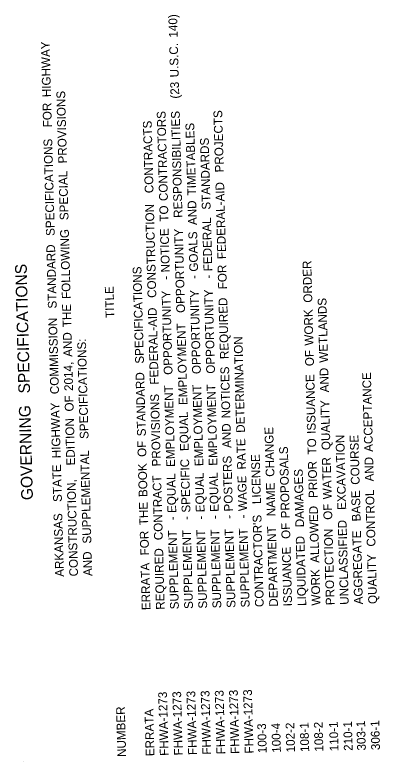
# Model space of a CAD drawing. Extents: x 1930579 to 1931706, y 595585 to 597808.
# Drawn here: x 1930907.1 to 1931148.4, y 595584.7 to 596077.6 of the extents above; entities that cross this region are included whole.
import ezdxf

# ---------------------------------------------------------------- set-up
doc = ezdxf.new("R2010")
doc.units = 0
doc.layers.add('Default', color=7, linetype='Continuous')
doc.layers.add('R_Annotation', color=7, linetype='Continuous')

msp = doc.modelspace()

# ---------------------------------------------------------------- linework, layer by layer
at = {"layer": 'R_Annotation'}
msp.add_line((1930912.52, 595584.68), (1930912.52, 595584.68), dxfattribs=at)

# ---------------------------------------------------------------- texts
at = {"layer": 'Default'}
for s, height, p in [(' 140)', 5.76, (1931014.7, 596060.51)), (' HIGHWAY', 5.76, (1930931.01, 596021.17)), (' U.S.C.', 5.76, (1931015.4, 596034.24)), (' (23', 5.76, (1931015.78, 596020.19)), (' PROVISIONS', 5.76, (1930941.55, 595977.38)), (' FOR', 5.76, (1930931.55, 596001.26)), (' CONTRACTORS', 5.76, (1931008.23, 595952.54)), (' RESPONSIBILITIES', 5.76, (1931017.89, 595941.45)), (' PROJECTS', 5.76, (1931045.18, 595971.46)), (' CONTRACTS', 5.76, (1930998.73, 595957.73)), (' TIMETABLES', 5.76, (1931026.86, 595956.25)), (' STANDARDS', 5.76, (1931036.47, 595946.85)), (' SPECIFICATIONS', 5.76, (1930933.47, 595929.52)), (' SPECIAL', 5.76, (1930942.56, 595939.95)), (' FEDERAL-AID', 5.76, (1931046.71, 595914.17)), (' CONSTRUCTION', 5.76, (1931000.58, 595888.58)), (' TO', 5.76, (1931008.6, 595938.95)), (' AND', 5.76, (1931027.38, 595936.68)), (' FEDERAL', 5.76, (1931037.57, 595906.16)), (' FOLLOWING', 5.76, (1930943.96, 595887.87)), (' NOTICE', 5.76, (1931009.5, 595905.41)), (' OPPORTUNITY', 5.76, (1931019.58, 595878.65)), (' GOALS', 5.76, (1931028.21, 595905.91)), (' STANDARD', 5.76, (1930934.76, 595881.54)), (' SPECIFICATIONS', 7.68, (1930917.18, 595824.77)), (' FOR', 5.76, (1931047.25, 595894.26)), (' ORDER', 5.76, (1931103.67, 595885.43)), (' SPECIFICATIONS', 5.76, (1930992.39, 595845.12)), (' -', 5.76, (1931009.63, 595900.55)), (' -', 5.76, (1931028.34, 595901.06)), (' -', 5.76, (1931037.7, 595901.31)), ('TITLE', 5.76, (1930972.79, 595877.46)), (' OPPORTUNITY', 5.76, (1931011.31, 595837.75)), (' OPPORTUNITY', 5.76, (1931030.03, 595838.26)), (' OPPORTUNITY', 5.76, (1931039.38, 595838.51)), (' REQUIRED', 5.76, (1931048.49, 595848.14)), (' WETLANDS', 5.76, (1931114.09, 595845.75)), (' THE', 5.76, (1930944.46, 595869.22)), (' FEDERAL-AID', 5.76, (1931002.12, 595831.28)), (' WORK', 5.76, (1931104.43, 595857.05)), (' COMMISSION', 5.76, (1930936.28, 595824.96)), (' EMPLOYMENT', 5.76, (1931021.21, 595817.82)), (' AND', 5.76, (1930944.98, 595849.65)), (' SPECIFICATIONS:', 5.76, (1930955.8, 595795.4)), (' DETERMINATION', 5.76, (1931059.16, 595799.46)), (' OF', 5.76, (1931104.79, 595843.47)), (' 2014,', 5.76, (1930945.59, 595827.11)), (' NOTICES', 5.76, (1931049.54, 595809)), (' AND', 5.76, (1931114.62, 595826.18)), (' STANDARD', 5.76, (1930993.68, 595797.14)), (' ISSUANCE', 5.76, (1931105.99, 595798.74)), (' ACCEPTANCE', 5.76, (1931143.77, 595786.87)), (' EMPLOYMENT', 5.76, (1931031.66, 595777.42)), (' EMPLOYMENT', 5.76, (1931041.02, 595777.68)), (' EMPLOYMENT', 5.76, (1931012.95, 595776.92)), (' OF', 5.76, (1930945.95, 595813.52)), (' PROVISIONS', 5.76, (1931003.57, 595777.23)), ('GOVERNING', 7.68, (1930918.99, 595757.15)), (' HIGHWAY', 5.76, (1930937.42, 595782.65)), (' QUALITY', 5.76, (1931115.64, 595788.05)), (' EQUAL', 5.76, (1931022.03, 595787.38)), (' EDITION', 5.76, (1930946.91, 595777.89)), (' AND', 5.76, (1931050.06, 595789.43)), (' CHANGE', 5.76, (1931078.66, 595770.4)), (' EXCAVATION', 5.76, (1931126.07, 595748.55)), (' COURSE', 5.76, (1931134.99, 595765.13)), (' OF', 5.76, (1930994.04, 595783.56)), (' RATE', 5.76, (1931059.81, 595775.22)), (' TO', 5.76, (1931106.36, 595785.15)), (' SUPPLEMENTAL', 5.76, (1930957.66, 595726.3)), (' PROPOSALS', 5.76, (1931088.76, 595742.97)), (' SPECIFIC', 5.76, (1931023.12, 595746.73)), (' POSTERS', 5.76, (1931051.19, 595747.48)), (' LICENSE', 5.76, (1931069.78, 595752.37)), (' WATER', 5.76, (1931116.52, 595755.58)), (' AND', 5.76, (1931144.29, 595767.29)), (' STATE', 5.76, (1930938.19, 595753.76)), (' BOOK', 5.76, (1930994.75, 595757.03)), (' PRIOR', 5.76, (1931107.13, 595756.4)), (' EQUAL', 5.76, (1931013.76, 595746.48)), (' EQUAL', 5.76, (1931032.48, 595746.98)), (' EQUAL', 5.76, (1931041.83, 595747.23)), (' DAMAGES', 5.76, (1931098.29, 595737.08)), ('           CONSTRUCTION,', 5.76, (1930949.45, 595683.2)), (' CONTRACT', 5.76, (1931004.88, 595728.51)), (' WAGE', 5.76, (1931060.55, 595747.74)), (' NAME', 5.76, (1931079.36, 595744.31)), (' BASE', 5.76, (1931135.64, 595740.89)), (' CONTROL', 5.76, (1931145.45, 595724.29)), (' THE', 5.76, (1930995.25, 595738.39)), (' OF', 5.76, (1931116.88, 595742)), (' ALLOWED', 5.76, (1931108.28, 595713.54)), ('           ARKANSAS', 5.76, (1930940.09, 595682.95)), (' -', 5.76, (1931013.89, 595741.62)), (' -', 5.76, (1931023.25, 595741.88)), (' -', 5.76, (1931032.61, 595742.13)), (' -', 5.76, (1931041.96, 595742.38)), (' -', 5.76, (1931051.32, 595742.63)), (' -', 5.76, (1931060.68, 595742.88)), ("CONTRACTOR'S", 5.76, (1931071.55, 595686.48)), ('DEPARTMENT', 5.76, (1931080.91, 595686.73)), (' OF', 5.76, (1931089.13, 595729.38)), ('UNCLASSIFIED', 5.76, (1931127.69, 595687.99)), (' FOR', 5.76, (1930995.79, 595718.48)), ('SUPPLEMENT', 5.76, (1931015.41, 595684.97)), ('SUPPLEMENT', 5.76, (1931024.77, 595685.23)), ('SUPPLEMENT', 5.76, (1931034.13, 595685.48)), ('SUPPLEMENT', 5.76, (1931043.48, 595685.73)), ('SUPPLEMENT', 5.76, (1931052.84, 595685.98)), ('SUPPLEMENT', 5.76, (1931062.2, 595686.23)), ('PROTECTION', 5.76, (1931118.34, 595687.74)), ('AGGREGATE', 5.76, (1931137.05, 595688.24)), ('LIQUIDATED', 5.76, (1931099.62, 595687.24)), ('REQUIRED', 5.76, (1931006.06, 595684.72)), ('ISSUANCE', 5.76, (1931090.27, 595686.98)), ('           AND', 5.76, (1930958.81, 595683.45)), ('QUALITY', 5.76, (1931146.41, 595688.49)), ('ERRATA', 5.76, (1930996.7, 595684.47)), ('WORK', 5.76, (1931108.98, 595687.49)), ('FHWA-1273', 5.76, (1931036.72, 595588.99)), ('FHWA-1273', 5.76, (1931046.07, 595589.24)), ('FHWA-1273', 5.76, (1931055.43, 595589.49)), ('FHWA-1273', 5.76, (1931064.79, 595589.74)), ('FHWA-1273', 5.76, (1931008.65, 595588.23)), ('FHWA-1273', 5.76, (1931018, 595588.48)), ('FHWA-1273', 5.76, (1931027.36, 595588.74)), ('NUMBER', 5.76, (1930980.58, 595587.48)), ('ERRATA', 5.76, (1930999.29, 595587.98)), ('306-1', 5.76, (1931148.35, 595591.98)), ('100-3', 5.76, (1931073.5, 595589.97)), ('100-4', 5.76, (1931082.85, 595590.23)), ('102-2', 5.76, (1931092.21, 595590.48)), ('108-1', 5.76, (1931101.57, 595590.73)), ('108-2', 5.76, (1931110.92, 595590.98)), ('110-1', 5.76, (1931120.93, 595591.25)), ('210-1', 5.76, (1931130.28, 595591.5)), ('303-1', 5.76, (1931138.99, 595591.73))]:
    msp.add_text(s, height=height, rotation=91.5377, dxfattribs=at).set_placement(p)

doc.saveas('drawing.dxf')
